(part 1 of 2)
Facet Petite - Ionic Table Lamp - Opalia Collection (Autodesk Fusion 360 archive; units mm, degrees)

design "Marble Base - Ionic Table Lamp - Ketra Ready - 120V - Opalia Collection" references "Facet Petite", "Arca Tall", "Chinois", "Arca Petite", "Ketra - A20 Tunable Lamp", "Marble Base - Ionic Table Lamp - Ketra Ready - 120V", "Trove - TL"
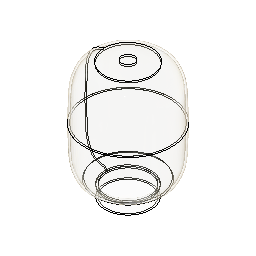
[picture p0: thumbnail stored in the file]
component_insert "Component Insert2"
component_insert "Component Insert3"
component_insert "Component Insert4"
component_insert "Component Insert5"
position "Position1"
component_insert "Component Insert6"
component_insert "Component Insert7"
component_insert "Component Insert8"

design "Arca Petite"
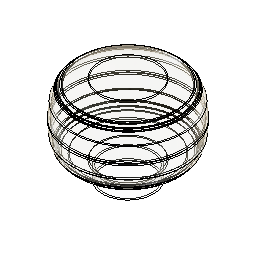
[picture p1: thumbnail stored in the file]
sketch "Sketch1" plane through (0, 0, 0) normal (0, 1, 0) x axis (1, 0, 0)
  line L1 (0, 101.6) -> (0, -101.6)
  line L2 (127, 0) -> (-127, 0)
  line L3 (63.5, 101.6) -> (-63.5, 101.6)
  perpendicular L1 L2
  parallel L2 L3
sketch "Sketch2" plane through (0, 0, 0) normal (0, 1, 0) x axis (1, 0, 0)
  line L1 (0, 101.6) -> (0, -101.6)
  line L2 (0, -76.2) -> (0, 101.6)
  line L3 (127, 0) -> (-127, 0)
  line L4 (114.3, 0) -> (-114.3, 0)
  line L5 (50.8, 101.6) -> (50.8, 63.5)
  line L6 (-50.8, 101.6) -> (50.8, 101.6)
  line L7 (-50.8, 63.5) -> (-50.8, 101.6)
  line L8 (63.5, 101.6) -> (-63.5, 101.6)
  line L9 (114.3, -76.2) -> (114.3, 63.5)
  line L10 (-114.3, -76.2) -> (114.3, -76.2)
  line L11 (-114.3, 63.5) -> (-114.3, -76.2)
  line L12 (-50.8, 63.5) -> (-114.3, 63.5)
  line L13 (114.3, 63.5) -> (50.8, 63.5)
  point P2 (0, 101.6)
  point P5 (0, 101.6)
  point P6 (0, -76.2)
  point P9 (-114.3, 0)
  point P10 (114.3, 0)
  point P11 (50.8, 101.6)
  point P19 (50.8, 63.5)
  coincident P2 P5
  coincident L1 P6
  coincident L3 P9
  coincident L3 P10
  vertical L5
  horizontal L6
  vertical L7
  coincident P11 L8
  horizontal L12
  vertical L9
  horizontal L10
  vertical L11
  coincident P19 L12
  collinear L12 L13
derived_base_feature "Derived Base Feature"
revolve "Revolve1" sketch "Sketch4" AlongAngle 360 bodies "Arca Petite"
shell "Shell1" innerThickness 3.81
component_from_bodies "Body->Comp"
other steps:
base_feature "Base Feature" bodies "Arca Petite"
create_component "CreateComponent1"
remove_body "RemoveBody1"
named bodies: "Arca Petite"

design "Neoprene Pad"
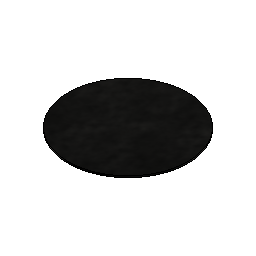
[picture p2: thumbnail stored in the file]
sketch "Sketch1" plane through (0, 0, 0) normal (0, 0, 1) x axis (1, 0, 0)
  circle C1 centre (0, 0) radius 57.15
  point P1 (0, 0)
  point P2 (0, 0)
  coincident P1 P2
extrude "Extrude1" new body sketch "Sketch1" along normal blind 1.5875 bodies "Neoprene Pad"
component_from_bodies "Body->Comp"
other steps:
base_feature "Base Feature" bodies "Neoprene Pad"
create_component "CreateComponent1"
remove_body "RemoveBody1"
named bodies: "Neoprene Pad"

design "T9 - Bulb"
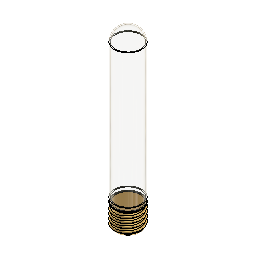
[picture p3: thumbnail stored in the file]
sketch "Sketch1" plane through (0, 0, 0) normal (0, 1, 0) x axis (1, 0, 0)
  line L1 (0, -166.37) -> (0, 0)
  line L2 (13.97, -13.97) -> (13.97, -152.4)
  line L3 (-13.97, -152.4) -> (-13.97, -13.97)
  line L4 (0, 0) -> (0, -166.37)
  line L5 (12.97, -13.97) -> (12.97, -152.4)
  line L6 (-12.97, -152.4) -> (-12.97, -13.97)
  line L7 (-12.3978, -10.16) -> (-13.4404, -10.16)
  line L8 (13.4404, -10.16) -> (12.3978, -10.16)
  arc A1 centre (0, -152.4) radius 13.97 clockwise from (13.97, -152.4) to (-13.97, -152.4)
  arc A2 centre (0, -152.4) radius 12.97 clockwise from (12.97, -152.4) to (-12.97, -152.4)
  arc A3 centre (0, -13.97) radius 13.97 clockwise from (13.4404, -10.16) to (13.97, -13.97)
  arc A4 centre (0, -13.97) radius 13.97 clockwise from (-13.97, -13.97) to (-13.4404, -10.16)
  arc A5 centre (0, -13.97) radius 12.97 clockwise from (12.3978, -10.16) to (12.97, -13.97)
  arc A6 centre (0, -13.97) radius 12.97 clockwise from (-12.97, -13.97) to (-12.3978, -10.16)
  point P1 (0, 0)
  point P2 (0, 0)
  point P3 (0, -166.37)
  point P10 (0, 0)
  point P17 (13.4404, -10.16)
  point P19 (12.3978, -10.16)
  point P4 (13.97, -152.4)
  point P5 (13.97, -13.97)
  coincident P1 P2
  vertical L1
  tangent L2 A3
  tangent L3 A3
  parallel L2 L3
  tangent L3 A1
  tangent L2 A1
  midpoint P3 A1
  coincident P1 P10
  perpendicular L1 L7
  coincident P17 L7
  concentric A3 A4
  coincident P10 A3
  concentric A1 A2
  tangent L5 A2
  tangent L5 A5
  tangent L6 A5
  tangent L6 A2
  coincident P19 L7
  concentric A5 A6
  collinear L7 L8
  dimension "d6" distance L2 L3 = 27.94
  dimension "d7" distance P4 P5 = 138.43
revolve "Revolve1" sketch "Sketch1" AlongAngle 360 bodies "T9"
derived_base_feature "Derived Base Feature" bodies "E26 Base"
align "Align1"
move "Move1"
component_from_bodies "Body->Comp1"
component_from_bodies "Body->Comp2"
copy_paste "CutPaste1"
copy_paste "CutPaste2"
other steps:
base_feature "Base Feature1" bodies "T9"
base_feature "Base Feature1" bodies "E26 Base"
create_component "CreateComponent1"
create_component "CreateComponent2"
remove_body "RemoveBody1"
create_component "CreateComponent3"
remove_body "RemoveBody2"
remove_instance "RemoveInstance1"
remove_instance "RemoveInstance2"
named bodies: "T9", "E26 Base"

design "Marble Base - Silicone Gasket"
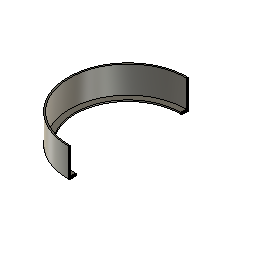
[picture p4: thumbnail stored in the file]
sketch "Sketch1" plane through (0, 0, 0) normal (0, 0, 1) x axis (1, 0, 0)
  circle C1 centre (0, 0) radius 53.34
  point P1 (0, 0)
  point P2 (0, 0)
  coincident P1 P2
extrude "Extrude1" new body sketch "Sketch1" along normal blind 25.4 bodies "Silicone Gasket"
shell "Shell1" innerThickness 1.27
sketch "Sketch2" plane through (0, 0, 1.27) normal (0, 0, 1) x axis (-1, 0, 0)
  circle C1 centre (0, 0) radius 52.07
  circle C2 centre (0, 0) radius 46.99
  concentric C1 C2
extrude "Extrude2" cut sketch "Sketch2" profile of C2 against normal blind 12.7
component_from_bodies "Body->Comp"
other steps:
base_feature "Base Feature" bodies "Silicone Gasket"
create_component "CreateComponent1"
remove_body "RemoveBody1"
named bodies: "Silicone Gasket"

design "2-Pole Plug End"
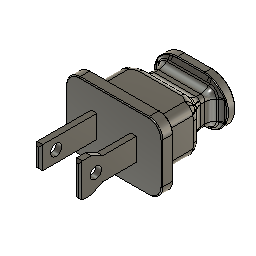
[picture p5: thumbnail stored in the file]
sketch "Sketch1" plane through (0, 0, 0) normal (0, 1, 0) x axis (1, 0, 0)
  line L1 (9.6837, 9.525) -> (-9.6837, 9.525)
  line L2 (13.4938, -5.715) -> (13.4938, 5.715)
  line L3 (-9.6837, -9.525) -> (9.6837, -9.525)
  line L4 (-13.4937, 5.715) -> (-13.4937, -5.715)
  line L5 (13.4938, -9.525) -> (-13.4937, 9.525)
  line L6 (-13.4937, -9.525) -> (13.4938, 9.525)
  arc A1 centre (-9.6837, -5.715) radius 3.81 clockwise from (-9.6837, -9.525) to (-13.4937, -5.715)
  arc A2 centre (9.6837, -5.715) radius 3.81 clockwise from (13.4938, -5.715) to (9.6837, -9.525)
  arc A3 centre (9.6837, 5.715) radius 3.81 clockwise from (9.6837, 9.525) to (13.4938, 5.715)
  arc A4 centre (-9.6837, 5.715) radius 3.81 clockwise from (-13.4937, 5.715) to (-9.6837, 9.525)
  point P6 (0, 0)
  point P1 (0, 0)
  point P5 (-13.4937, -9.525)
  point P4 (13.4938, -9.525)
  point P3 (13.4938, 9.525)
  point P2 (-13.4937, 9.525)
  horizontal L1
  perpendicular L1 L2
  parallel L1 L3
  parallel L2 L4
  coincident L5 P6
  coincident L6 P6
  coincident P1 P6
  coincident P5 L4
  coincident P5 L3
  tangent L4 A1
  tangent L3 A1
  coincident P4 L3
  coincident P4 L2
  tangent L3 A2
  tangent L2 A2
  equal A1 A2
  coincident P3 L2
  coincident P3 L1
  tangent L2 A3
  tangent L1 A3
  equal A1 A3
  coincident P2 L1
  coincident P2 L4
  tangent L1 A4
  tangent L4 A4
  equal A1 A4
  dimension "d1" distance P4 P5 = 26.9875
  dimension "d2" distance P2 P5 = 19.05
  dimension "d3" radius A1 = 3.81
extrude "Extrude1" new body sketch "Sketch1" profile of L1 L2 L3 L4 A1 A2 A3 A4 along normal blind 3.175
sketch "Sketch2" plane through (0, 3.175, 0) normal (0, 1, 0) x axis (-1, 0, 0)
  line L1 (9.6837, -9.525) -> (-9.6837, -9.525)
  line L2 (13.4937, 5.715) -> (13.4937, -5.715)
  line L3 (-9.6837, 9.525) -> (9.6837, 9.525)
  line L4 (-13.4938, -5.715) -> (-13.4938, 5.715)
  line L5 (10.16, -6.35) -> (-10.16, -6.35)
  line L6 (10.16, 6.35) -> (10.16, -6.35)
  line L7 (-10.16, 6.35) -> (10.16, 6.35)
  line L8 (-10.16, -6.35) -> (-10.16, 6.35)
  line L9 (10.16, 6.35) -> (-10.16, -6.35)
  line L10 (-10.16, 6.35) -> (10.16, -6.35)
  arc A1 centre (-9.6837, -5.715) radius 3.81 clockwise from (-9.6837, -9.525) to (-13.4938, -5.715)
  arc A2 centre (9.6837, -5.715) radius 3.81 clockwise from (13.4937, -5.715) to (9.6837, -9.525)
  arc A3 centre (9.6837, 5.715) radius 3.81 clockwise from (9.6837, 9.525) to (13.4937, 5.715)
  arc A4 centre (-9.6837, 5.715) radius 3.81 clockwise from (-13.4938, 5.715) to (-9.6837, 9.525)
  point P18 (0, 0)
  point P1 (0, 0)
  horizontal L5
  perpendicular L5 L6
  parallel L5 L7
  parallel L6 L8
  coincident L9 P18
  coincident L10 P18
  coincident P1 P18
extrude "Extrude2" add sketch "Sketch2" profile of L5 L6 L7 L8 along normal blind 9.525
sketch "Sketch3" plane through (0, 12.7, 0) normal (0, 1, 0) x axis (-1, 0, 0)
  line L1 (-10.16, -6.35) -> (-10.16, 6.35)
  line L2 (10.16, -6.35) -> (-10.16, -6.35)
  line L3 (10.16, 6.35) -> (10.16, -6.35)
  line L4 (-10.16, 6.35) -> (10.16, 6.35)
  line L5 (-7.1437, 3.9688) -> (7.1437, 3.9688)
  line L6 (-7.1437, -3.9688) -> (-7.1437, 3.9688)
  line L7 (7.1437, -3.9688) -> (-7.1437, -3.9688)
  line L8 (7.1437, 3.9688) -> (7.1437, -3.9688)
  line L9 (-7.1437, -3.9688) -> (7.1437, 3.9688)
  line L10 (7.1437, -3.9688) -> (-7.1437, 3.9688)
  point P10 (0, 0)
  point P1 (0, 0)
  point P8 (-7.1437, -3.9688)
  point P9 (7.1437, -3.9688)
  point P7 (-7.1437, 3.9688)
  horizontal L5
  perpendicular L5 L6
  parallel L5 L7
  parallel L6 L8
  coincident L9 P10
  coincident L10 P10
  coincident P1 P10
  dimension "d8" distance P8 P9 = 14.2875
  dimension "d9" distance P7 P8 = 7.9375
extrude "Extrude3" add sketch "Sketch3" profile of L5 L6 L7 L8 along normal blind 11.1125
fillet "Fillet1" radius 2.286 1.27 0.254
chamfer "Chamfer1" distance 3.429
fillet "Fillet2" radius 2.54 1.905
sketch "Sketch4" plane through (0, 23.8125, 0) normal (0, 1, 0) x axis (-1, 0, 0)
  line L1 (-7.1437, -2.6987) -> (-7.1437, 2.6987)
  line L2 (5.8737, -3.9688) -> (-5.8737, -3.9688)
  line L3 (7.1437, 2.6987) -> (7.1437, -2.6987)
  line L4 (-5.8737, 3.9688) -> (5.8737, 3.9688)
  line L5 (-3.81, 6.604) -> (3.81, 6.604)
  line L6 (3.81, -6.604) -> (-3.81, -6.604)
  line L7 (-10.414, 0) -> (10.414, 0)
  arc A1 centre (-5.8737, 2.6987) radius 1.27 clockwise from (-7.1437, 2.6987) to (-5.8737, 3.9688)
  arc A2 centre (-5.8737, -2.6987) radius 1.27 clockwise from (-5.8737, -3.9688) to (-7.1437, -2.6987)
  arc A3 centre (5.8737, -2.6987) radius 1.27 clockwise from (7.1437, -2.6987) to (5.8737, -3.9688)
  arc A4 centre (5.8737, 2.6987) radius 1.27 clockwise from (5.8737, 3.9688) to (7.1437, 2.6987)
  arc A5 centre (-3.81, 0) radius 6.604 clockwise from (-3.81, -6.604) to (-3.81, 6.604)
  arc A6 centre (3.81, 0) radius 6.604 clockwise from (3.81, 6.604) to (3.81, -6.604)
  point P20 (10.414, 0)
  point P21 (-10.414, 0)
  tangent L5 A5
  tangent A5 L6
  parallel L5 L6
  tangent L6 A6
  tangent L5 A6
  midpoint A6 P20
  midpoint A5 P21
  perpendicular L1 L7
extrude "Extrude4" add sketch "Sketch4" profile of A1 L1 A2 L2 A3 L3 A4 L4 L5 A5 L6 A6 against normal blind 2.286
chamfer "Chamfer2" distance 1.778
fillet "Fillet3" radius 1.778
fillet "Fillet4" radius 0.254
fillet "Fillet5" radius 0.254
fillet "Fillet6" radius 0.254
fillet "Fillet7" radius 3.175
sketch "Sketch5" plane through (0, 0, 0) normal (0, -1, 0) x axis (1, 0, 0)
  line L1 (-13.2397, -5.715) -> (-13.2397, 5.715)
  line L2 (9.6837, -9.271) -> (-9.6837, -9.271)
  line L3 (13.2397, 5.715) -> (13.2397, -5.715)
  line L4 (-9.6837, 9.271) -> (9.6837, 9.271)
  line L5 (-6.35, -3.175) -> (-6.35, 3.175)
  line L6 (6.35, 3.175) -> (-6.35, -3.175)
  line L7 (-6.35, 3.175) -> (6.35, -3.175)
  line L8 (-4.7625, 3.175) -> (-6.35, 3.175)
  line L9 (-4.7625, -3.175) -> (-4.7625, 3.175)
  line L10 (-6.35, -3.175) -> (-4.7625, -3.175)
  line L11 (-6.35, 3.175) -> (-6.35, -3.175)
  line L12 (0, -3.302) -> (0, 3.81)
  line L13 (4.7625, -3.175) -> (4.7625, 3.175)
  line L14 (4.7625, 3.175) -> (6.35, 3.175)
  line L15 (6.35, -3.175) -> (6.35, 3.175)
  line L16 (6.35, -3.175) -> (4.7625, -3.175)
  arc A1 centre (-9.6837, 5.715) radius 3.556 clockwise from (-13.2397, 5.715) to (-9.6837, 9.271)
  arc A2 centre (-9.6837, -5.715) radius 3.556 clockwise from (-9.6837, -9.271) to (-13.2397, -5.715)
  arc A3 centre (9.6837, -5.715) radius 3.556 clockwise from (13.2397, -5.715) to (9.6837, -9.271)
  arc A4 centre (9.6837, 5.715) radius 3.556 clockwise from (9.6837, 9.271) to (13.2397, 5.715)
  point P18 (0, 0)
  point P1 (0, 0)
  point P14 (-6.35, -3.175)
  point P27 (6.35, -3.175)
  point P17 (-6.35, 3.175)
  point P26 (6.35, 3.175)
  point P19 (-4.7625, 3.175)
  point P24 (4.7625, 3.175)
  point P20 (-4.7625, -3.175)
  point P25 (4.7625, -3.175)
  point P21 (-6.35, -3.175)
  point P28 (6.35, -3.175)
  point P15 (6.35, -3.175)
  point P16 (6.35, 3.175)
  coincident L6 P18
  coincident L7 P18
  coincident P1 P18
  horizontal L8
  vertical L9
  horizontal L10
  vertical L11
  vertical L12
  symmetric P14 L12 P27
  symmetric P17 L12 P26
  symmetric P19 L12 P24
  symmetric P20 L12 P25
  symmetric P21 L12 P28
  dimension "d36" distance P15 P16 = 6.35
  dimension "d37" distance P17 P19 = 1.5875
extrude "Extrude5" add sketch "Sketch5" profile of L5 L8 L9 L10 L11 L13 L14 L15 L16 along normal blind 15.875
sketch "Sketch7" plane through (0, 0, 3.175) normal (0, 0, 1) x axis (-1, 0, 0)
  line L1 (-4.7625, 0) -> (-6.35, 0)
  line L2 (-4.7625, 15.875) -> (-4.7625, 0)
  line L3 (-6.35, 15.875) -> (-4.7625, 15.875)
  line L4 (-6.35, 0) -> (-6.35, 15.875)
  line L5 (-4.7625, 15.875) -> (-6.35, 15.875)
  line L6 (-4.7625, 9.525) -> (-4.7625, 15.875)
  line L7 (-6.35, 9.525) -> (-4.7625, 9.525)
  line L8 (-6.35, 15.875) -> (-6.35, 9.525)
  point P5 (-6.35, 15.875)
  point P6 (-6.35, 15.875)
  point P9 (-6.35, 9.525)
  horizontal L5
  vertical L6
  horizontal L7
  vertical L8
  coincident P5 P6
  dimension "d45" distance P6 P9 = 6.35
extrude "Extrude7" add sketch "Sketch7" profile of L2 L3 L4 L5 L6 L7 L8 against normal blind 7.9375 and along normal blind 1.5875
chamfer "Chamfer3" distance 0.508
chamfer "Chamfer4" distance 0.635 distance 0.635
sketch "Sketch6" plane through (6.35, 0, 0) normal (1, 0, 0) x axis (0, 1, 0)
  line L1 (0, -3.175) -> (-9.525, -3.175)
  line L2 (0, 3.175) -> (0, -3.175)
  line L3 (-9.525, 3.175) -> (0, 3.175)
  line L4 (-15.367, -4.6355) -> (-15.367, 4.6355)
  line L5 (-11.43, 0) -> (-16.002, 0)
  line L6 (-9.525, -4.7625) -> (-15.24, -4.7625)
  line L7 (-9.525, -3.175) -> (-9.525, -4.7625)
  line L8 (-9.525, 4.7625) -> (-9.525, 3.175)
  line L9 (-15.24, 4.7625) -> (-9.525, 4.7625)
  line L10 (-15.24, -4.7625) -> (-15.367, -4.6355)
  line L11 (-15.367, 4.6355) -> (-15.24, 4.7625)
  circle C1 centre (-11.43, 0) radius 1.5875
  point P9 (-11.43, 0)
  point P10 (-11.43, 0)
  perpendicular L4 L5
  coincident P9 P10
  dimension "d42" diameter C1 = 3.175
extrude "Extrude6" cut sketch "Sketch6" profile of C1 against normal blind 20.32
chamfer "Chamfer5" distance 3.175 distance 1.5875 distance 3.175 distance 1.5875
component_from_bodies "Body->Comp"
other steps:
base_feature "Base Feature" bodies "2-Pole Plug End"
create_component "CreateComponent1"
remove_body "RemoveBody1"
named bodies: "2-Pole Plug End"

design "Facet Petite"
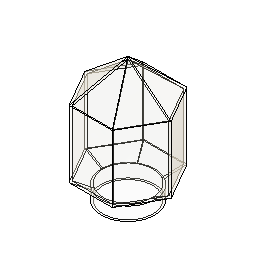
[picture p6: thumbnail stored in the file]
sketch "Sketch7" plane through (0, 0, 0) normal (1, 0, 0) x axis (0, 1, 0)
sketch "Sketch8" plane through (0, 0, 0) normal (0, 0, 1) x axis (1, 0, 0)
  circle C1 centre (0, 0) radius 50.8
  point P1 (0, 0)
  point P2 (0, 0)
  coincident P1 P2
  dimension "d17" diameter C1 = 101.6
extrude "Extrude5" new body sketch "Sketch8" along normal blind 25.4 and against normal blind 25.4
work_plane "WorkPlane1" AlongDistance 17.78
sketch "Sketch10" plane through (0, 0, 25.4) normal (0, 0, 1) x axis (-1, 0, 0)
  circle C1 centre (0, 0) radius 50.8
sketch "Sketch12" plane through (0, 0, 43.18) normal (0, 0, 1) x axis (1, 0, 0)
  line L1 (-82.1223, 0) -> (-41.0612, 71.12)
  line L2 (-41.0612, -71.12) -> (-82.1223, 0)
  line L3 (41.0612, -71.12) -> (-41.0612, -71.12)
  line L4 (82.1223, 0) -> (41.0612, -71.12)
  line L5 (41.0612, 71.12) -> (82.1223, 0)
  line L6 (-41.0612, 71.12) -> (41.0612, 71.12)
  point P1 (0, 0)
  point P8 (0, 0)
  coincident P1 P8
  dimension "d22" distance P8 L6 = 71.12
sketch "Sketch15" plane through (0, 0, 0) normal (0, 1, 0) x axis (1, 0, 0)
  line L1 (53.7365, -21.6801) -> (82.1223, -43.18)
  line L2 (-50.8, -25.4) -> (-82.1223, -43.18)
  point P2 (82.1223, -43.18)
  point P3 (82.1223, -43.18)
  point P5 (-82.1223, -43.18)
  point P7 (-82.1223, -43.18)
  point P6 (-50.8, -25.4)
  point P8 (-50.8, -25.4)
  coincident P2 P3
  coincident P5 P7
  coincident P6 P8
sketch "Sketch17" plane through (0, 0, 25.4) normal (0, 0, 1) x axis (-1, 0, 0)
  line L1 (51.3255, 0) -> (0, 0)
  line L2 (73.3235, 0) -> (0, 0)
  line L3 (-41.0612, -71.12) -> (-25.4, -43.9941)
  line L4 (-36.6617, -63.5) -> (-25.4, -43.9941)
  line L5 (78.4305, 0) -> (0, 0)
  line L6 (41.0612, -71.12) -> (25.4, -43.9941)
  line L7 (25.4, 43.9941) -> (41.0612, 71.12)
  line L8 (73.3235, 0) -> (0, 0)
  line L9 (-25.4, 43.9941) -> (-41.0612, 71.12)
  line L10 (0, 0) -> (0, 0)
  circle C1 centre (0, 0) radius 50.8
  point P1 (0, 0)
  point P4 (0, 0)
  point P2 (-41.0612, -71.12)
  point P6 (-41.0612, -71.12)
  point P3 (0, 0)
  point P7 (0, 0)
  point P9 (-25.4, -43.9941)
  point P12 (41.0612, -71.12)
  point P13 (41.0612, -71.12)
  point P15 (25.4, -43.9941)
  point P16 (41.0612, 71.12)
  point P17 (41.0612, 71.12)
  point P18 (25.4, 43.9941)
  point P19 (-41.0612, 71.12)
  point P20 (-41.0612, 71.12)
  point P21 (0, 0)
  point P23 (-25.4, 43.9941)
  point P25 (0, 0)
  point P24 (0, 0)
  point P26 (0, 0)
  horizontal L1
  coincident P1 P4
  coincident P2 P6
  horizontal L2
  coincident P3 P7
  coincident C1 P9
  coincident P12 P13
  horizontal L5
  coincident C1 P15
  coincident P16 P17
  coincident C1 P18
  coincident P19 P20
  horizontal L8
  coincident P1 P21
  coincident C1 P23
  coincident P1 P25
  coincident P24 P26
extrude "Extrude6" new body sketch "Sketch12" along normal blind 127
work_plane "WorkPlane2" AlongDistance 66.04
sketch "Sketch18" plane through (0, 0, 236.22) normal (0, 0, 1) x axis (1, 0, 0)
  line L1 (41.0612, -71.12) -> (0, 0)
  line L2 (82.1223, 0) -> (0, 0)
  line L3 (41.0612, 71.12) -> (0, 0)
  line L4 (-41.0612, 71.12) -> (0, 0)
  line L5 (-82.1223, 0) -> (0, 0)
  line L6 (-41.0612, -71.12) -> (0, 0)
  point P1 (0, 0)
  point P3 (0, 0)
  point P2 (41.0612, -71.12)
  point P4 (41.0612, -71.12)
  point P6 (0, 0)
  point P5 (82.1223, 0)
  point P7 (82.1223, 0)
  point P9 (0, 0)
  point P8 (41.0612, 71.12)
  point P10 (41.0612, 71.12)
  point P12 (0, 0)
  point P11 (-41.0612, 71.12)
  point P13 (-41.0612, 71.12)
  point P15 (0, 0)
  point P14 (-82.1223, 0)
  point P16 (-82.1223, 0)
  point P18 (0, 0)
  point P17 (-41.0612, -71.12)
  point P19 (-41.0612, -71.12)
  coincident P1 P3
  coincident P2 P4
  coincident P1 P6
  coincident P5 P7
  coincident P1 P9
  coincident P8 P10
  coincident P1 P12
  coincident P11 P13
  coincident P1 P15
  coincident P14 P16
  coincident P1 P18
  coincident P17 P19
loft "Loft1"
loft "Loft2" sketch "Sketch17"
component_from_bodies "Body->Comp"
extrude "Extrude1" cut of existing geometry blind -25.4
shell "Shell2" innerThickness 3.81
fillet "Fillet1" radius 7.62
fillet "Fillet2" radius 6.35
fillet "Fillet3" radius 6.35
fillet "Fillet4" radius 6.35
fillet "Fillet5" radius 6.35
fillet "Fillet6" radius 6.35
fillet "Fillet7" radius 3.81
fillet "Fillet8" radius 6.35
fillet "Fillet9" radius 6.35
fillet "Fillet10" radius 6.35
fillet "Fillet11" radius 6.35
fillet "Fillet12" radius 6.35
fillet "Fillet13" radius 2.286
shell "Shell1" innerThickness 2.54
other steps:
base_feature "Base Feature"
create_component "CreateComponent3"
remove_body "RemoveBody2"

design "Chinois"
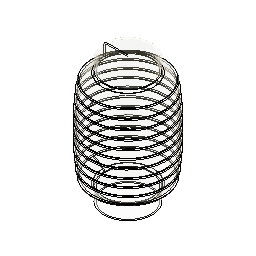
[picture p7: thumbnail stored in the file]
named bodies: "Chinois"

design "Marble Base - Plastic Insert"
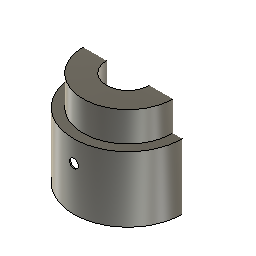
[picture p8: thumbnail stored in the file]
sketch "Sketch1" plane through (0, 0, 0) normal (0, 0, 1) x axis (1, 0, 0)
  circle C1 centre (0, 0) radius 50.038
  point P1 (0, 0)
  point P2 (0, 0)
  coincident P1 P2
  dimension "d1" diameter C1 = 100.076
extrude "Extrude1" new body sketch "Sketch1" along normal blind 72.898 bodies "Plastic Insert"
shell "Shell1" innerThickness 1.016
work_plane "WorkPlane1" AlongDistance 18.034
sketch "Sketch2" plane through (0, 0, 90.932) normal (0, 0, 1) x axis (1, 0, 0)
  circle C1 centre (0, 0) radius 20.701
  point P1 (0, 0)
  point P2 (0, 0)
  coincident P1 P2
  dimension "d6" diameter C1 = 41.402
extrude "Extrude2" add sketch "Sketch2" against normal blind 65.024
shell "Shell2" innerThickness 1.016
sketch "Sketch3" plane through (0, 0, 0) normal (0, 1, 0) x axis (1, 0, 0)
  line L1 (5.08, -20.32) -> (-5.08, -20.32)
  line L2 (5.08, 20.32) -> (5.08, -20.32)
  line L3 (-5.08, 20.32) -> (5.08, 20.32)
  line L4 (-5.08, -20.32) -> (-5.08, 20.32)
  line L5 (5.08, 20.32) -> (-5.08, -20.32)
  line L6 (-5.08, 20.32) -> (5.08, -20.32)
  point P6 (0, 0)
  point P1 (0, 0)
  horizontal L1
  perpendicular L1 L2
  parallel L1 L3
  parallel L2 L4
  coincident L5 P6
  coincident L6 P6
  coincident P1 P6
extrude "Extrude3" cut sketch "Sketch3" profile of L1 L2 L3 L4 along normal blind 91.44
sketch "Sketch4" plane through (0, 0, 0) normal (0, 1, 0) x axis (1, 0, 0)
  line L1 (0, -40.64) -> (0, 0)
  circle C1 centre (0, -40.64) radius 4.064
  point P1 (0, 0)
  point P2 (0, 0)
  point P3 (0, -40.64)
  point P4 (0, -40.64)
  coincident P1 P2
  vertical L1
  coincident P3 P4
  dimension "d12" diameter C1 = 8.128
work_plane "WorkPlane2" AlongDistance -91.44
sketch "Sketch5" plane through (0, -91.44, 0) normal (0, 1, 0) x axis (1, 0, 0)
  circle C1 centre (0, -40.64) radius 4.064
extrude "Extrude4" cut sketch "Sketch5" along normal blind 63.5
sketch "Sketch6" plane through (0, 0, 26.924) normal (0, 0, 1) x axis (-1, 0, 0)
  circle C1 centre (0, 0) radius 19.685
  circle C2 centre (0, 0) radius 5.461
  concentric C1 C2
  dimension "d16" diameter C2 = 10.922
extrude "Extrude5" cut sketch "Sketch6" profile of C2 against normal blind 15.24
sketch "Sketch7" plane through (0, 0, 72.898) normal (0, 0, 1) x axis (-1, 0, 0)
  circle C1 centre (0, 0) radius 20.701
  circle C2 centre (0, 0) radius 50.038
  circle C3 centre (0, 0) radius 20.701
  circle C4 centre (0, 0) radius 45.72
  point P1 (0, 0)
  point P3 (0, 0)
  point P4 (0, 0)
  coincident P1 P3
  coincident P1 P4
extrude "Extrude6" add sketch "Sketch7" profile of C1 C3 C4 along normal blind 18.034
sketch "Sketch8" plane through (0, 0, 71.882) normal (0, 0, -1) x axis (1, 0, 0)
  circle C1 centre (0, 0) radius 20.701
  circle C2 centre (0, 0) radius 49.022
  circle C3 centre (0, 0) radius 20.701
  circle C4 centre (0, 0) radius 44.704
  point P1 (0, 0)
  point P3 (0, 0)
  point P4 (0, 0)
  coincident P1 P3
  coincident P1 P4
  dimension "d21" diameter C4 = 89.408
extrude "Extrude7" cut sketch "Sketch8" profile of C1 C3 C4 against normal blind 17.78
extrude "Extrude8" add of existing geometry blind 9.398
extrude "Extrude9" cut of existing geometry blind -9.398
component_from_bodies "Body->Comp"
offset_faces "OffsetFaces1" distance 4.445
offset_faces "OffsetFaces2" distance -4.445
offset_faces "OffsetFaces3" distance 3.175
offset_faces "OffsetFaces4" distance 3.175
offset_faces "OffsetFaces5" distance 3.175
offset_faces "OffsetFaces6" distance -3.175
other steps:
base_feature "Base Feature" bodies "Plastic Insert"
create_component "CreateComponent1"
remove_body "RemoveBody1"
named bodies: "Plastic Insert"

design "Arca Tall"
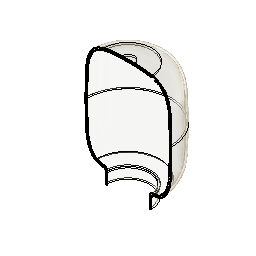
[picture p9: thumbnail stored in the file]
derived_base_feature "Derived Base Feature" bodies "Balon"
work_plane "WorkPlane1" AlongDistance 0
sketch "Sketch1" plane through (0, 0, 0) normal (0, 1, 0) x axis (1, 0, 0)
  line L1 (0, 317.5) -> (0, 2.9083)
  curve K1 (-82.9821, 124.2212) -> (-50.8, 237.8015)
  curve K2 (-51.0925, 237.681) -> (-50.8, 237.8015)
  curve K3 (-51.3855, 237.5558) -> (-51.0925, 237.681)
  curve K4 (-54.7608, 236.0513) -> (-51.3855, 237.5558)
  curve K5 (-57.9615, 234.05) -> (-54.7608, 236.0513)
  curve K6 (-67.2727, 226.749) -> (-57.9615, 234.05)
  curve K7 (-69.0552, 224.2615) -> (-67.2727, 226.749)
  curve K8 (-72.1872, 218.7832) -> (-69.0552, 224.2615)
  curve K9 (-74.1213, 215.1556) -> (-72.1872, 218.7832)
  curve K10 (-78.3031, 204.3965) -> (-74.1213, 215.1556)
  curve K11 (-79.7275, 197.3397) -> (-78.3031, 204.3965)
  curve K12 (-81.3333, 185.4664) -> (-79.7275, 197.3397)
  curve K13 (-81.6254, 178.4008) -> (-81.3333, 185.4664)
  curve K14 (-82.49, 152.2133) -> (-81.6254, 178.4008)
  curve K15 (-82.9821, 136.067) -> (-82.49, 152.2133)
  curve K16 (-82.9821, 124.2212) -> (-82.9821, 136.067)
  curve K17 (50.8, 237.7999) -> (82.9821, 124.2212)
  curve K18 (82.9821, 140.3031) -> (82.9821, 124.2212)
  curve K19 (81.9353, 169.4257) -> (82.9821, 140.3031)
  curve K20 (81.3621, 183.6489) -> (81.9353, 169.4257)
  curve K21 (80.9478, 189.8724) -> (81.3621, 183.6489)
  curve K22 (77.8147, 206.9858) -> (80.9478, 189.8724)
  curve K23 (74.9652, 213.2153) -> (77.8147, 206.9858)
  curve K24 (69.4688, 224.1531) -> (74.9652, 213.2153)
  curve K25 (67.2512, 226.458) -> (69.4688, 224.1531)
  curve K26 (61.5696, 231.3138) -> (67.2512, 226.458)
  curve K27 (57.377, 234.6711) -> (61.5696, 231.3138)
  curve K28 (52.0556, 237.2628) -> (57.377, 234.6711)
  curve K29 (51.4313, 237.5413) -> (52.0556, 237.2628)
  curve K30 (50.8, 237.7999) -> (51.4313, 237.5413)
  line L2 (-50.8, 317.5) -> (-50.8, 237.8015)
  line L3 (50.8, 317.5) -> (50.8, 237.7999)
  line L4 (-19.0713, 6.7501) -> (-19.0713, 6.7501)
  curve K31 (82.9821, 124.1958) -> (40.1509, 7.3012)
  curve K32 (41.8198, 7.6176) -> (40.1509, 7.3012)
  curve K33 (43.2113, 8.0663) -> (41.8198, 7.6176)
  curve K34 (47.0139, 9.2854) -> (43.2113, 8.0663)
  curve K35 (47.3314, 9.3805) -> (47.0139, 9.2854)
  curve K36 (50.1192, 10.3272) -> (47.3314, 9.3805)
  curve K37 (51.833, 11.0085) -> (50.1192, 10.3272)
  curve K38 (57.8313, 14.1895) -> (51.833, 11.0085)
  curve K39 (61.4491, 17.0488) -> (57.8313, 14.1895)
  curve K40 (66.8203, 21.5867) -> (61.4491, 17.0488)
  curve K41 (68.5372, 23.5528) -> (66.8203, 21.5867)
  curve K42 (71.2201, 27.8971) -> (68.5372, 23.5528)
  curve K43 (74.7424, 33.8984) -> (71.2201, 27.8971)
  curve K44 (78.2342, 44.8406) -> (74.7424, 33.8984)
  curve K45 (79.6792, 50.3463) -> (78.2342, 44.8406)
  curve K46 (81.3558, 63.5576) -> (79.6792, 50.3463)
  curve K47 (81.6386, 70.4415) -> (81.3558, 63.5576)
  curve K48 (82.4897, 96.2198) -> (81.6386, 70.4415)
  curve K49 (82.9814, 112.3523) -> (82.4897, 96.2198)
  curve K50 (82.9821, 124.1958) -> (82.9814, 112.3523)
  curve K51 (-40.1501, 7.301) -> (-82.9821, 124.1958)
  curve K52 (-82.9813, 110.5256) -> (-82.9821, 124.1958)
  curve K53 (-82.2545, 88.8594) -> (-82.9813, 110.5256)
  curve K54 (-81.6277, 70.519) -> (-82.2545, 88.8594)
  curve K55 (-81.3572, 64.3441) -> (-81.6277, 70.519)
  curve K56 (-79.4149, 46.8924) -> (-81.3572, 64.3441)
  curve K57 (-76.5204, 38.9768) -> (-79.4149, 46.8924)
  curve K58 (-73.5142, 32.2947) -> (-76.5204, 38.9768)
  curve K59 (-72.5556, 30.3818) -> (-73.5142, 32.2947)
  curve K60 (-69.7914, 25.3691) -> (-72.5556, 30.3818)
  curve K61 (-68.3824, 23.4028) -> (-69.7914, 25.3691)
  curve K62 (-64.5419, 19.5456) -> (-68.3824, 23.4028)
  curve K63 (-62.3002, 17.7646) -> (-64.5419, 19.5456)
  curve K64 (-53.6583, 11.1976) -> (-62.3002, 17.7646)
  curve K65 (-49.6968, 10.1396) -> (-53.6583, 11.1976)
  curve K66 (-43.4141, 8.1331) -> (-49.6968, 10.1396)
  curve K67 (-41.9704, 7.6516) -> (-43.4141, 8.1331)
  curve K68 (-40.1963, 7.3098) -> (-41.9704, 7.6516)
  curve K69 (-40.1732, 7.3054) -> (-40.1963, 7.3098)
  curve K70 (-40.1501, 7.301) -> (-40.1732, 7.3054)
  line L5 (-82.9821, 124.1958) -> (-82.9821, 124.2212)
  line L6 (82.9821, 124.2212) -> (82.9821, 124.1958)
  line L7 (0, 317.5) -> (-50.8, 317.5)
  line L8 (7.2015, 3.048) -> (0, 3.048)
  line L9 (0, 3.048) -> (-7.2015, 3.048)
  arc A1 centre (0, 188.595) radius 185.6867 clockwise from (-7.2015, 3.048) to (-40.1502, 7.301)
  arc A2 centre (0, 188.595) radius 185.6867 clockwise from (40.151, 7.3012) to (7.2015, 3.048)
  point P38 (-40.1502, 7.301)
  point P43 (40.1509, 7.3012)
  point P62 (-40.1501, 7.301)
  point P81 (40.151, 7.3012)
  point P84 (0, 3.048)
  vertical L1
  horizontal L4
  coincident P38 K51
  symmetric L1 A1 A2
  coincident A2 P43
  coincident A1 P62
  coincident K31 P81
  perpendicular L2 L7
  horizontal L8
  coincident L1 P84
  horizontal L9
revolve "Revolve1" sketch "Sketch1" AlongAngle 360
shell "Shell1" innerThickness 3.81
fillet "Fillet1" radius 6.35 bodies "Balon v3"
offset_faces "OffsetFaces1" distance -50.8
move "Move1"
move "Move2"
component_from_bodies "Body->Comp1"
component_from_bodies "Body->Comp2"
sketch "Sketch2" plane through (0, 0, 0) normal (0, 1, 0) x axis (1, 0, 0)
  line L1 (-85.5221, 124.2212) -> (-85.5221, 124.1961)
  curve K1 (-58.9057, 236.4383) -> (-50.8, 241.7989)
  curve K2 (-50.8, 241.554) -> (-50.8, 241.7989)
  curve K3 (-50.904, 240.933) -> (-50.8, 241.554)
  curve K4 (-51.2936, 240.2837) -> (-50.904, 240.933)
  curve K5 (-51.734, 239.7561) -> (-51.2936, 240.2837)
  curve K6 (-53.328, 238.5038) -> (-51.734, 239.7561)
  curve K7 (-54.0892, 238.1997) -> (-53.328, 238.5038)
  curve K8 (-58.9057, 236.4383) -> (-54.0892, 238.1997)
  curve K9 (-89.3309, 124.2212) -> (-58.9057, 236.4383)
  curve K10 (-62.6336, 234.9735) -> (-58.9057, 236.4383)
  curve K11 (-65.581, 233.1032) -> (-62.6336, 234.9735)
  curve K12 (-73.0224, 227.0019) -> (-65.581, 233.1032)
  curve K13 (-74.8981, 224.836) -> (-73.0224, 227.0019)
  curve K14 (-78.1104, 219.6097) -> (-74.8981, 224.836)
  curve K15 (-80.2663, 215.561) -> (-78.1104, 219.6097)
  curve K16 (-84.0943, 205.8277) -> (-80.2663, 215.561)
  curve K17 (-85.4655, 200.1154) -> (-84.0943, 205.8277)
  curve K18 (-87.4092, 188.5789) -> (-85.4655, 200.1154)
  curve K19 (-87.7349, 182.3889) -> (-87.4092, 188.5789)
  curve K20 (-88.4233, 165.9645) -> (-87.7349, 182.3889)
  curve K21 (-89.328, 138.6964) -> (-88.4233, 165.9645)
  curve K22 (-89.3309, 124.2212) -> (-89.328, 138.6964)
  line L2 (-89.3309, 124.1958) -> (-89.3309, 124.2212)
  curve K23 (-46.5001, 7.301) -> (-89.3309, 124.1958)
  curve K24 (-89.3314, 112.4293) -> (-89.3309, 124.1958)
  curve K25 (-88.8181, 95.3068) -> (-89.3314, 112.4293)
  curve K26 (-88.346, 81.2892) -> (-88.8181, 95.3068)
  curve K27 (-88.0298, 70.4902) -> (-88.346, 81.2892)
  curve K28 (-87.1514, 58.328) -> (-88.0298, 70.4902)
  curve K29 (-86.3326, 50.6119) -> (-87.1514, 58.328)
  curve K30 (-81.0932, 33.6688) -> (-86.3326, 50.6119)
  curve K31 (-77.3163, 27.4309) -> (-81.0932, 33.6688)
  curve K32 (-74.8955, 23.6666) -> (-77.3163, 27.4309)
  curve K33 (-73.5108, 22.0741) -> (-74.8955, 23.6666)
  curve K34 (-70.2346, 19.0457) -> (-73.5108, 22.0741)
  curve K35 (-64.8094, 14.3548) -> (-70.2346, 19.0457)
  curve K36 (-56.6696, 10.3041) -> (-64.8094, 14.3548)
  curve K37 (-54.0053, 9.483) -> (-56.6696, 10.3041)
  curve K38 (-49.1487, 7.9411) -> (-54.0053, 9.483)
  curve K39 (-48.3482, 7.6526) -> (-49.1487, 7.9411)
  curve K40 (-46.5001, 7.301) -> (-48.3482, 7.6526)
  line L3 (0, 266.7) -> (0, 0)
  line L4 (0, 3.048) -> (-7.7894, 3.048)
  line L5 (-50.8, 266.7) -> (-50.8, 241.7989)
  line L6 (0, 266.7) -> (-50.8, 266.7)
  arc A1 centre (-6.9779, 188.7329) radius 185.6867 clockwise from (-7.7894, 3.048) to (-46.5001, 7.301)
  point P1 (0, 0)
  point P44 (0, 0)
  point P46 (0, 3.048)
  point P5 (-50.8, 241.554)
  point P49 (0, 266.7)
  coincident P1 P44
  coincident L3 P46
  coincident P5 L5
  coincident L3 P49
revolve "Revolve2" sketch "Sketch2" AlongAngle 360 bodies "Balon v3"
shell "Shell2" innerThickness 3.81
component_from_bodies "Body->Comp3"
remove_instance "RemoveInstance1"
remove_instance "RemoveInstance2"
sketch "Sketch1" plane through (0, 0, 0) normal (0, 1, 0) x axis (1, 0, 0)
  line L1 (-6.35, 3.048) -> (-14.1394, 3.048)
  curve K1 (-52.8501, 7.301) -> (-95.6809, 124.1958)
  curve K2 (-95.6814, 112.4293) -> (-95.6809, 124.1958)
  curve K3 (-95.1681, 95.3068) -> (-95.6814, 112.4293)
  curve K4 (-94.696, 81.2892) -> (-95.1681, 95.3068)
  curve K5 (-94.3798, 70.4902) -> (-94.696, 81.2892)
  curve K6 (-93.5014, 58.328) -> (-94.3798, 70.4902)
  curve K7 (-92.6826, 50.6119) -> (-93.5014, 58.328)
  curve K8 (-87.4432, 33.6688) -> (-92.6826, 50.6119)
  curve K9 (-83.6663, 27.4309) -> (-87.4432, 33.6688)
  curve K10 (-81.2455, 23.6666) -> (-83.6663, 27.4309)
  curve K11 (-79.8608, 22.0741) -> (-81.2455, 23.6666)
  curve K12 (-76.5846, 19.0457) -> (-79.8608, 22.0741)
  curve K13 (-71.12, 13.97) -> (-76.5846, 19.0457)
  curve K14 (-62.23, 10.16) -> (-71.12, 13.97)
  curve K15 (-60.3553, 9.483) -> (-62.23, 10.16)
  curve K16 (-55.4987, 7.9411) -> (-60.3553, 9.483)
  curve K17 (-54.6982, 7.6526) -> (-55.4987, 7.9411)
  curve K18 (-52.8501, 7.301) -> (-54.6982, 7.6526)
  line L2 (-95.6809, 124.1958) -> (-95.6809, 124.2212)
  line L3 (0, 266.7) -> (0, 0)
  line L4 (0, 3.048) -> (-6.35, 3.048)
  line L5 (-95.6809, 124.2466) -> (-95.6809, 124.2212)
  line L6 (-50.8, 266.7) -> (-50.8, 241.7989)
  line L7 (0, 266.7) -> (-50.8, 266.7)
  curve K19 (-71.6837, 232.5587) -> (-50.8, 241.7989)
  curve K20 (-50.8, 237.8015) -> (-50.8, 241.7989)
  curve K21 (-53.6019, 236.5654) -> (-50.8, 237.8015)
  curve K22 (-59.7861, 236.0598) -> (-53.6019, 236.5654)
  curve K23 (-64.4375, 235.2772) -> (-59.7861, 236.0598)
  curve K24 (-69.8917, 233.4707) -> (-64.4375, 235.2772)
  curve K25 (-71.6837, 232.5587) -> (-69.8917, 233.4707)
  curve K26 (-71.6837, 232.5587) -> (-95.6809, 124.2466)
  curve K27 (-95.6814, 136.0132) -> (-95.6809, 124.2466)
  curve K28 (-95.1681, 153.1357) -> (-95.6814, 136.0132)
  curve K29 (-94.696, 167.1533) -> (-95.1681, 153.1357)
  curve K30 (-94.3798, 177.9523) -> (-94.696, 167.1533)
  curve K31 (-93.5014, 190.1145) -> (-94.3798, 177.9523)
  curve K32 (-92.6826, 197.8306) -> (-93.5014, 190.1145)
  curve K33 (-87.4432, 214.7737) -> (-92.6826, 197.8306)
  curve K34 (-83.6663, 221.0115) -> (-87.4432, 214.7737)
  curve K35 (-81.2455, 224.7759) -> (-83.6663, 221.0115)
  curve K36 (-79.8608, 226.3684) -> (-81.2455, 224.7759)
  curve K37 (-77.083, 228.9361) -> (-79.8608, 226.3684)
  curve K38 (-75.5537, 230.2778) -> (-77.083, 228.9361)
  curve K39 (-71.6837, 232.5587) -> (-75.5537, 230.2778)
  curve K40 (-50.8, 244.8458) -> (-50.8, 244.8469)
  curve K41 (-50.8, 244.8465) -> (-50.8, 244.8469)
  curve K42 (-50.8, 244.8462) -> (-50.8, 244.8465)
  curve K43 (-50.8, 244.8458) -> (-50.8, 244.8462)
  arc A1 centre (-13.3279, 188.7329) radius 185.6867 clockwise from (-14.1394, 3.048) to (-52.8501, 7.301)
  point P26 (0, 3.048)
  point P33 (-50.8, 237.8015)
  point P35 (-50.8, 237.8015)
  point P40 (-71.6837, 232.5587)
  point P53 (-50.8, 244.8458)
  coincident L3 P26
  perpendicular L3 L4
  coincident P33 P35
  coincident K19 P40
  coincident L6 P53
sketch "Sketch2" plane through (0, 0, 0) normal (0, 1, 0) x axis (1, 0, 0)
  line L1 (-95.6809, 124.1958) -> (-95.6809, 124.2212)
  line L2 (0, 266.7) -> (-50.8, 266.7)
  curve K1 (-58.9317, 239.3909) -> (-50.8, 244.8469)
  curve K2 (-50.8, 244.602) -> (-50.8, 244.8469)
  curve K3 (-50.904, 243.981) -> (-50.8, 244.602)
  curve K4 (-51.2936, 243.3317) -> (-50.904, 243.981)
  curve K5 (-51.734, 242.8041) -> (-51.2936, 243.3317)
  curve K6 (-53.328, 241.5518) -> (-51.734, 242.8041)
  curve K7 (-54.0892, 241.2477) -> (-53.328, 241.5518)
  curve K8 (-58.9317, 239.3909) -> (-54.0892, 241.2477)
  line L3 (-50.8, 266.7) -> (-50.8, 244.8458)
  curve K9 (-52.8501, 7.301) -> (-95.6809, 124.1958)
  curve K10 (-95.6814, 112.4293) -> (-95.6809, 124.1958)
  curve K11 (-95.1681, 95.3068) -> (-95.6814, 112.4293)
  curve K12 (-94.696, 81.2892) -> (-95.1681, 95.3068)
  curve K13 (-94.3798, 70.4902) -> (-94.696, 81.2892)
  curve K14 (-93.5014, 58.328) -> (-94.3798, 70.4902)
  curve K15 (-92.6826, 50.6119) -> (-93.5014, 58.328)
  curve K16 (-87.4432, 33.6688) -> (-92.6826, 50.6119)
  curve K17 (-83.6663, 27.4309) -> (-87.4432, 33.6688)
  curve K18 (-81.2455, 23.6666) -> (-83.6663, 27.4309)
  curve K19 (-79.8608, 22.0741) -> (-81.2455, 23.6666)
  curve K20 (-76.5846, 19.0457) -> (-79.8608, 22.0741)
  curve K21 (-73.7599, 16.6033) -> (-76.5846, 19.0457)
  curve K22 (-65.532, 11.7145) -> (-73.7599, 16.6033)
  curve K23 (-60.3553, 9.483) -> (-65.532, 11.7145)
  curve K24 (-55.4987, 7.9411) -> (-60.3553, 9.483)
  curve K25 (-54.6982, 7.6526) -> (-55.4987, 7.9411)
  curve K26 (-52.8501, 7.301) -> (-54.6982, 7.6526)
  line L4 (-95.6809, 124.2466) -> (-95.6809, 124.2212)
  line L5 (0, 3.048) -> (-6.35, 3.048)
  line L6 (-6.35, 3.048) -> (-14.1394, 3.048)
  curve K27 (-58.9317, 239.3909) -> (-95.6809, 124.2466)
  curve K28 (-95.6814, 136.0132) -> (-95.6809, 124.2466)
  curve K29 (-95.1681, 153.1357) -> (-95.6814, 136.0132)
  curve K30 (-94.696, 167.1533) -> (-95.1681, 153.1357)
  curve K31 (-94.3798, 177.9523) -> (-94.696, 167.1533)
  curve K32 (-93.5014, 190.1145) -> (-94.3798, 177.9523)
  curve K33 (-92.6826, 197.8306) -> (-93.5014, 190.1145)
  curve K34 (-87.4432, 214.7737) -> (-92.6826, 197.8306)
  curve K35 (-83.6663, 221.0115) -> (-87.4432, 214.7737)
  curve K36 (-81.2455, 224.7759) -> (-83.6663, 221.0115)
  curve K37 (-79.8608, 226.3684) -> (-81.2455, 224.7759)
  curve K38 (-76.5846, 229.3968) -> (-79.8608, 226.3684)
  curve K39 (-73.7599, 231.8391) -> (-76.5846, 229.3968)
  curve K40 (-65.833, 236.5491) -> (-73.7599, 231.8391)
  curve K41 (-61.4585, 238.4785) -> (-65.833, 236.5491)
  curve K42 (-58.9317, 239.3909) -> (-61.4585, 238.4785)
  line L7 (0, 3.048) -> (0, 266.7)
  arc A1 centre (-13.3279, 188.7329) radius 185.6867 clockwise from (-14.1394, 3.048) to (-52.8501, 7.301)
  point P52 (-50.8, 244.8458)
  coincident K1 P52
  perpendicular L5 L7
revolve "Revolve1" sketch "Sketch1" AlongAngle 360 bodies "Balon v3.3"
shell "Shell1" innerThickness 3.81
revolve "Revolve2" sketch "Sketch2" AlongAngle 360 bodies "Balon v3.2"
shell "Shell2" innerThickness 3.81
component_from_bodies "Body->Comp1"
component_from_bodies "Body->Comp2"
position "Position1"
remove_instance "RemoveInstance1" bodies "Balon v3"
remove_instance "RemoveInstance2"
move "Move1"
position "Position2" bodies "Balon v3"
sketch "Sketch3" plane through (0, 0, 0) normal (0, 1, 0) x axis (1, 0, 0)
  line L1 (0, 50.8) -> (0, -304.8)
  line L2 (127, 50.8) -> (127, -304.8)
  line L3 (-127, 50.8) -> (-127, -304.8)
  line L4 (139.7, 25.4) -> (-139.7, 25.4)
  line L5 (139.7, -292.1) -> (-139.7, -292.1)
  line L6 (95.25, 50.8) -> (95.25, -304.8)
  vertical L1
  dimension "d6" = 127
  dimension "d12" = -127
  dimension "d17" distance L4 L5 = 317.5
  dimension "d18" = 95.25
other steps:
base_feature "Base Feature1" bodies "Balon v3.3"
base_feature "Base Feature1" bodies "Balon v3.2"
base_feature "Base Feature1" bodies "Balon"
base_feature "Base Feature1" bodies "Balon v3"
base_feature "Base Feature1" bodies "Balon v2"
create_component "CreateComponent1"
remove_body "RemoveBody1"
create_component "CreateComponent2"
remove_body "RemoveBody2"
create_component "CreateComponent3"
remove_body "RemoveBody3" bodies "Balon v3"
create_component "CreateComponent1"
create_component "CreateComponent2"
remove_body "RemoveBody1" bodies "Balon v3"
create_component "CreateComponent3"
remove_body "RemoveBody2" bodies "Balon v3"
named bodies: "Balon", "Balon v2", "Balon v3", "Balon v3.3", "Balon v3.2"

design "Marble Base - Ionic Table Lamp - Ketra Ready - 120V" references "Marble Base - Ionic Table Lamp - 120V"
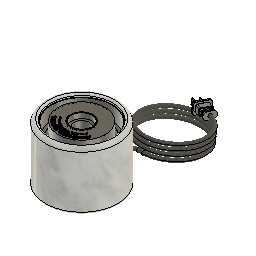
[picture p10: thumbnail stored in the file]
external_derived "ExternalDerived1" bodies "Coiled - SVT (Blk Fabric)", "Body1", "Marble Base", "Body2", "Silicone Gasket", "Plastic Insert"
derived_instance "DerivedInstance1"
derived_instance "DerivedInstance2"
derived_instance "DerivedInstance3"
derived_instance "DerivedInstance4"
derived_instance "DerivedInstance5"
derived_instance "DerivedInstance6"
derived_instance "DerivedInstance7"
derived_instance "DerivedInstance8"
derived_instance "DerivedInstance9"
derived_instance "DerivedInstance10"
derived_instance "DerivedInstance11"
derived_instance "DerivedInstance12"
offset_faces "OffsetFaces1" distance 3.81
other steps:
derived_base_feature "Derived Base Feature1" bodies "Rubber Grommet"
derived_base_feature "Derived Base Feature1" bodies "Neoprene Pad"
derived_base_feature "Derived Base Feature1" bodies "2-Pole Plug End"
derived_base_feature "Derived Base Feature1" bodies "Body1"
derived_base_feature "Derived Base Feature1" bodies "Body1", "Body2"
derived_base_feature "Derived Base Feature1" bodies "Body1"
derived_base_feature "Derived Base Feature1" bodies "Silicone Gasket"
derived_base_feature "Derived Base Feature1" bodies "Plastic Insert"
derived_base_feature "Derived Base Feature1" bodies "Body1"
derived_base_feature "Derived Base Feature1" bodies "Body1"
derived_base_feature "Derived Base Feature1" bodies "Coiled - SVT (Blk Fabric)"
derived_base_feature "Derived Base Feature1" bodies "Marble Base"
create_component "CreateComponent1"
create_component "CreateComponent2"
create_component "CreateComponent3"
create_component "CreateComponent4"
create_component "CreateComponent5"
create_component "CreateComponent6"
create_component "CreateComponent7"
create_component "CreateComponent8"
create_component "CreateComponent9"
create_component "CreateComponent10"
create_component "CreateComponent11"
create_component "CreateComponent12"
named bodies: "Coiled - SVT (Blk Fabric)", "Marble Base", "Body1", "Body2", "Plastic Insert", "Silicone Gasket", "Neoprene Pad", "2-Pole Plug End", "Rubber Grommet"

design "Rubber Grommet"
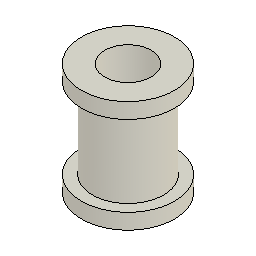
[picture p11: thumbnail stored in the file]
sketch "Sketch1" plane through (0, 0, 0) normal (0, 1, 0) x axis (1, 0, 0)
  line L1 (0, 3.048) -> (0, -12.7)
  line L2 (5.842, 0.508) -> (5.842, -12.7)
  line L3 (3.81, 3.048) -> (3.81, -15.24)
  line L4 (7.62, -12.7) -> (7.62, -15.24)
  line L5 (7.62, 3.048) -> (7.62, 0.508)
  line L6 (7.62, 0.508) -> (5.842, 0.508)
  line L7 (7.62, -12.7) -> (5.842, -12.7)
  line L8 (7.62, -15.24) -> (3.81, -15.24)
  line L9 (7.62, 3.048) -> (3.81, 3.048)
  vertical L1
  collinear L4 L5
revolve "Revolve1" sketch "Sketch1" AlongAngle 360 bodies "Rubber Grommet"
component_from_bodies "Body->Comp"
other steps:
base_feature "Base Feature" bodies "Rubber Grommet"
create_component "CreateComponent1"
remove_body "RemoveBody1"
named bodies: "Rubber Grommet"

design "Marble Base - Ionic Table Lamp - 120V" references "T9 - Bulb", "Arca Tall", "Facet Petite", "T9-5In", "Marble Base - Plastic Insert", "Rubber Grommet", "Neoprene Pad", "2-Pole Plug End", "Trove - TL", "Balon v2", "Chinois", "Marble Base - Silicone Gasket"
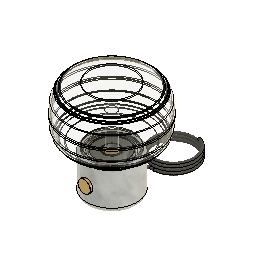
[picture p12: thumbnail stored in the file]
sketch "Sketch1" plane through (0, 0, 0) normal (0, 0, 1) x axis (1, 0, 0)
  circle C1 centre (0, 0) radius 63.5
  point P1 (0, 0)
  point P2 (0, 0)
  coincident P1 P2
extrude "Extrude1" new body sketch "Sketch1" along normal blind 101.6 bodies "Marble Base"
sketch "Sketch2" plane through (0, 0, 101.6) normal (0, 0, 1) x axis (-1, 0, 0)
  circle C1 centre (0, 0) radius 63.5
  circle C2 centre (0, 0) radius 53.975
  concentric C1 C2
  dimension "d3" diameter C2 = 107.95
extrude "Extrude2" cut sketch "Sketch2" profile of C2 against normal blind 34.925
sketch "Sketch3" plane through (0, 0, 66.675) normal (0, 0, 1) x axis (-1, 0, 0)
  circle C1 centre (0, 0) radius 53.975
  circle C2 centre (0, 0) radius 49.276
  point P1 (0, 0)
  point P3 (0, 0)
  coincident P1 P3
  dimension "d6" diameter C2 = 98.552
extrude "Extrude3" cut sketch "Sketch3" profile of C2 against normal blind 45.72
sketch "Sketch4" plane through (0, 0, 0) normal (0, 1, 0) x axis (1, 0, 0)
  circle C1 centre (0, -50.8) radius 3.81
  dimension "d9" diameter C1 = 7.62
extrude "Extrude4" cut sketch "Sketch4" against normal blind 127
sketch "Sketch5" plane through (0, 0, 0) normal (0, 1, 0) x axis (1, 0, 0)
  line L1 (0, -25.4) -> (0, 0)
  line L2 (0, -30.48) -> (0, -25.4)
  circle C1 centre (0, -30.48) radius 5.08
  point P1 (0, 0)
  point P2 (0, 0)
  point P4 (0, -30.48)
  point P5 (0, -30.48)
  coincident P1 P2
  vertical L1
  parallel L1 L2
  coincident P4 P5
  dimension "d12" diameter C1 = 10.16
extrude "Extrude5" cut sketch "Sketch5" profile of C1 along normal blind 114.3
fillet "Fillet1" radius 6.35 3.175 4.064
derived_base_feature "Derived Base Feature1" bodies "Rotary Switch"
derived_base_feature "Derived Base Feature1" bodies "Coiled - SVT (Blk Fabric)"
derived_base_feature "Derived Base Feature1" bodies "Glass Globe"
derived_base_feature "Derived Base Feature1" bodies "Metal Housing"
derived_base_feature "Derived Base Feature1" bodies "Metal Socket Cover"
derived_base_feature "Derived Base Feature1" bodies "Porcelain Socket"
derived_base_feature "Derived Base Feature1" bodies "Brass Dial - Dimmer Knob"
component_from_bodies "Body->Comp1"
offset_faces "OffsetFaces1" distance 12.7
offset_faces "OffsetFaces2" distance -12.7
derived_base_feature "Derived Base Feature1" bodies "Solitaire Petite"
move "Move1"
offset_faces "OffsetFaces1" distance 20.32
move "Move2"
extrude "Extrude6" add of existing geometry blind 25.4
offset_faces "OffsetFaces2" distance -3.81
fillet "Fillet2" radius 2.54
move "Move3"
derived_base_feature "Derived Base Feature2" bodies "Facet Petite"
move "Move4"
offset_faces "OffsetFaces1" distance 2.54
move "Move1"
derived_base_feature "Derived Base Feature1" bodies "Body1"
derived_base_feature "Derived Base Feature1" bodies "Body1"
derived_base_feature "Derived Base Feature1" bodies "Body1"
derived_base_feature "Derived Base Feature1" bodies "Body1"
derived_base_feature "Derived Base Feature1" bodies "Body1"
derived_base_feature "Derived Base Feature1" bodies "Body1", "Body2"
derived_base_feature "Derived Base Feature1" bodies "Body1"
position "Position1"
external_derived "ExternalDerived5" bodies "Plastic Insert"
derived_instance "DerivedInstance15"
offset_faces "OffsetFaces1" distance 3.81
offset_faces "OffsetFaces2" distance -1.0414
move "Move6"
external_derived "ExternalDerived6" sketch "Sketch3" bodies "Silicone Gasket"
derived_instance "DerivedInstance16"
offset_faces "OffsetFaces3" distance -10.795
move "Move1"
move_face "MoveFace1"
position "Position2"
position "Position3"
position "Position4"
position "Position5"
move "Move2"
position "Position6"
offset_faces "OffsetFaces2" distance -7.62
chamfer "Chamfer1" distance 0.381
remove_instance "RemoveInstance1"
remove_instance "RemoveInstance2"
remove_instance "RemoveInstance3"
remove_instance "RemoveInstance4"
move "Move1"
derived_base_feature "Derived Base Feature5" bodies "Oculo Petite"
align "Align1"
external_derived "ExternalDerived8"
derived_base_feature "Derived Base Feature7" bodies "Balon v2"
derived_base_feature "Derived Base Feature8" bodies "Balon v3"
align "Align3"
align "Align4"
external_derived "ExternalDerived10"
component_insert "Component Insert1"
position "Position7"
position "Position8"
derived_base_feature "Derived Base Feature11" bodies "Trove - TL"
move "Move10"
move "Move11"
remove_instance "RemoveInstance5"
split "Split1" bodies "Trove - TL (1)"
remove_body "RemoveBody2"
remove_body "RemoveBody3"
external_derived "ExternalDerived13" bodies "Trove - TL"
derived_instance "DerivedInstance20"
remove_body "RemoveBody4"
remove_body "RemoveBody5"
component_insert "Component Insert2"
component_insert "Component Insert3"
component_from_bodies "Body->Comp2"
remove_body "RemoveBody7"
move "Move12"
move "Move13"
sketch "Sketch6" plane through (0, 0, 97.917) normal (0, 0, 1) x axis (-1, 0, 0)
  circle C1 centre (0, 0) radius 41.275
  circle C2 centre (0, 0) radius 19.685
  arc A1 centre (0, 0) radius 29.3982 clockwise from (-27.6283, 10.0466) to (27.6283, 10.0466)
  arc A2 centre (0, 0) radius 26.2232 clockwise from (-24.6444, 8.9616) to (24.6444, 8.9616)
  arc A3 centre (0, 0) radius 32.5732 clockwise from (-30.6121, 11.1317) to (30.6121, 11.1317)
  arc A4 centre (0, 0) radius 35.7482 clockwise from (-33.596, 12.2167) to (33.596, 12.2167)
  point P1 (0, 0)
  point P3 (0, 0)
  coincident P1 P3
  dimension "d37" = -3.175
  dimension "d38" = 3.175
  dimension "d39" = 6.35
  dimension "d40" Text1-Height = 2.54
  dimension "d41" Text2-Height = 2.54
  dimension "d42" Text3-Height = 2.54
  dimension "d43" Text4-Height = 2.54
extrude "Extrude1" cut sketch "Sketch6" against normal blind 0.254
external_derived "ExternalDerived14" bodies "Rubber Grommet"
derived_instance "DerivedInstance19"
external_derived "ExternalDerived15" bodies "2-Pole Plug End"
derived_instance "DerivedInstance18"
external_derived "ExternalDerived16" bodies "Neoprene Pad"
derived_instance "DerivedInstance17"
position "Position9"
position "Position10"
position "Position11"
position "Position12"
external_derived "ExternalDerived17" bodies "Chinois"
derived_instance "DerivedInstance21"
position "Position13"
move "Move3"
remove_body "RemoveBody8"
component_insert "Component Insert4"
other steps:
derived_base_feature "Derived Base Feature1" bodies "Trove - TL"
derived_base_feature "Derived Base Feature1" bodies "Chinois"
derived_base_feature "Derived Base Feature1" bodies "Rubber Grommet"
derived_base_feature "Derived Base Feature1" bodies "2-Pole Plug End"
derived_base_feature "Derived Base Feature1" bodies "Neoprene Pad"
move "Move1"
base_feature "Base Feature1" bodies "Oculo Petite"
derived_base_feature "Derived Base Feature1" bodies "Plastic Insert"
derived_base_feature "Derived Base Feature1" bodies "Silicone Gasket"
base_feature "Base Feature1" bodies "Marble Base"
move "Move8"
derived_base_feature "Derived Base Feature"
create_component "CreateComponent1"
create_component "CreateComponent2"
create_component "CreateComponent3"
